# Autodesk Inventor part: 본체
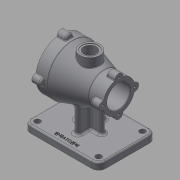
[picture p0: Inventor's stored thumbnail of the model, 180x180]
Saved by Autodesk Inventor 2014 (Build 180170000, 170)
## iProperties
Created: 2020-12
Part Number: 본체
Material: Generic
Document SubType Name: Modeling
Designer: kh
Density: 1 g/cm^3
Appearance: Default
Mass: 382.358 g
Surface Area: 851.644 cm^2
Volume: 382.358 cm^3
Author: kh
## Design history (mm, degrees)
sketch "스케치1"
  geometry: L1 (-65, -50)-(65, -50); L2 (65, -50)-(65, 50); L3 (65, 50)-(-65, 50); L4 (-65, 50)-(-65, -50); L5 (-65, -50)-(65, 50); L6 (65, -50)-(-65, 50); 1 further point
  constraints: 12 end point, 2 midpoint, 2 parallel, 1 horizontal, 1 perpendicular
  dimensions: "d0" = 130 distance of L2.end L3.end; "d1" = 100 distance of L1.end L2.end
extrude "돌출1" new body sketch "스케치1" distance "d2" = 12; taper "d3" = 0 deg
fillet "모깎기1" dims "d4" = 12
hole "구멍1" diameter "d7" = 10; stored, may be unused: countersink angle "d11" = 90 deg, drill point angle "d13" = 118 deg; dims "d5" = 10, "d6" = 10, "d8" = 6, "d9" = 4, "d10" = 2, "d12" = 8
sketch "스케치2"
  geometry: L1 (-50, 82)-(50, 82); L2 (-50, 82)-(-50, 126); L3 (-50, 126)-(-30, 126); L4 (-30, 126)-(25, 109.5); L5 (25, 109.5)-(50, 109.5); L6 (50, 109.5)-(50, 82); L7 (53, 0)-(-53, 0) reference; 3 further points
  constraints: 12 end point, 2 midpoint, 2 parallel, 2 perpendicular, 1 horizontal, 1 vertical alignment
  dimensions: "d18" = 88 diameter of L3 L1; "d19" = 82 distance between parallel lines of L7 L1; "d20" = 55 diameter of L5 L1; "d21" = 100 distance between parallel lines of L6 L2; "d23" = 20 horizontal distance of L3.end L1.start; "d133" = 25 distance from line of L4.end L6
revolve "회전1" sketch "스케치2" stored, may be unused: angle "d22" = 90 deg
node "작업 평면2"
node "작업 평면3"
hole "구멍2" diameter "d39" = 64; stored, may be unused: countersink angle "d43" = 90 deg, drill point angle "d45" = 0 deg; dims "d37" = 10, "d38" = 10, "d40" = 6, "d41" = 4, "d42" = 2, "d44" = 23
hole "구멍3" diameter "d48" = 52; stored, may be unused: countersink angle "d52" = 90 deg, drill point angle "d54" = 0 deg; dims "d46" = 10, "d47" = 10, "d49" = 6, "d50" = 4, "d51" = 2, "d53" = 47
hole "구멍4" diameter "d57" = 40; stored, may be unused: countersink angle "d61" = 90 deg, drill point angle "d63" = 0 deg; dims "d55" = 10, "d56" = 10, "d58" = 6, "d59" = 4, "d60" = 2, "d62" = 30
sketch "스케치9"
  geometry: C1 r 20 at (0, 0) reference; C2 r 7 at (0, 27.5); 2 further points
  constraints: 2 vertical alignment, 1 centre point, 1 other
  dimensions: "d65" = 7 radius of C2
extrude "돌출4" join sketch "스케치9" distance "d66" = 15; taper "d67" = 0 deg
sketch "스케치10"
  geometry: C1 r 32 at (0, 0) reference; C2 r 7 at (-44, 0); 2 further points
  constraints: 2 horizontal alignment, 1 centre point, 1 other
  dimensions: "d71" = 7 radius of C2
extrude "돌출5" join sketch "스케치10" distance "d72" = 15; taper "d73" = 0 deg
hole "구멍5" diameter "d79" = 4.134; stored, may be unused: countersink angle "d83" = 90 deg, drill point angle "d85" = 118 deg; dims "d77" = 10, "d78" = 10, "d80" = 9, "d81" = 4, "d82" = 2, "d84" = 11
hole "구멍6" diameter "d91" = 4.134; stored, may be unused: countersink angle "d95" = 90 deg, drill point angle "d97" = 118 deg; dims "d89" = 10, "d90" = 10, "d92" = 9, "d93" = 4, "d94" = 2, "d96" = 11
node "작업 평면4"
sketch "스케치11"
  geometry: C1 r 17 at (0, 0); 1 further point
  constraints: 1 centre point, 1 coincident
  dimensions: "d102" = 34 diameter of C1
extrude "돌출6" join sketch "스케치11" stored distance "d103" = 15; taper "d104" = 0 deg
hole "구멍7" diameter "d107" = 22; stored, may be unused: countersink angle "d111" = 90 deg, drill point angle "d113" = 0 deg; dims "d105" = 10, "d106" = 10, "d108" = 9, "d109" = 28, "d110" = 1, "d112" = 27.25
fillet "모깎기2" dims "d114" = 3
fillet "모깎기3" dims "d115" = 3
fillet "모깎기4" dims "d116" = 1
fillet "모깎기5" dims "d120" = 3
fillet "모깎기6" dims "d121" = 1
fillet "모깎기8" dims "d126" = 3
chamfer "모따기1" distance "d127" = 1; stored, may be unused: second distance "d128" = 2, angle "d129" = 45 deg
fillet "모깎기9" dims "d130" = 1
fillet "모깎기10" dims "d131" = 3
sketch "스케치12"
  geometry: L1 (4, 25)-(-4, 25); L2 (-4, 25)-(-4, -25); L3 (-4, -25)-(4, -25); L4 (4, -25)-(4, 25); L5 (4, 25)-(-4, -25); L6 (-4, 25)-(4, -25); 2 further points
  constraints: 12 end point, 3 midpoint, 2 parallel, 1 horizontal, 1 perpendicular
  dimensions: "d134" = 8 distance of L3.end L2.end; "d135" = 50 distance between parallel lines of L1 L3
extrude "돌출7" join sketch "스케치12" stored distance "d136" = 15; taper "d137" = 0 deg
sketch "스케치13"
  geometry: L1 (24, 4)-(-24, 4); L2 (-24, 4)-(-24, -4); L3 (-24, -4)-(24, -4); L4 (24, -4)-(24, 4); L5 (24, 4)-(-24, -4); L6 (-24, 4)-(24, -4); 1 further point
  constraints: 12 end point, 2 midpoint, 2 parallel, 1 horizontal, 1 perpendicular
  dimensions: "d138" = 48 distance between parallel lines of L2 L4; "d139" = 8 distance between parallel lines of L1 L3
extrude "돌출8" join sketch "스케치13" stored distance "d140" = 15; taper "d141" = 0 deg
fillet "모깎기12" dims "d142" = 4
fillet "모깎기13" dims "d143" = 4
sketch "스케치14"
  geometry: L1 (53, 50)-(-53, 50) reference; 2 further points
  constraints: 1 vertical alignment, 1 other
  dimensions: "d144" = 10 distance from line of point (0, 40) L1
feature "엠보싱1" sketch "스케치14" dims "d1" = 100, "d145" = 0.5, "d146" = 0
node "솔리드1"
pattern_linear "직사각형 패턴1"
pattern_circular "원형 패턴1" dims angle "d69" = 360 deg
pattern_circular "원형 패턴2" dims angle "d75" = 360 deg
pattern_circular "원형 패턴3" dims angle "d87" = 360 deg
pattern_circular "원형 패턴4" dims angle "d99" = 360 deg
pattern_circular "원형 패턴5" dims angle "d118" = 360 deg
pattern_circular "원형 패턴6" dims angle "d123" = 360 deg
other parameters: "d101" = 127
